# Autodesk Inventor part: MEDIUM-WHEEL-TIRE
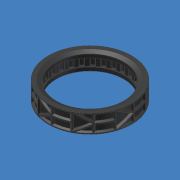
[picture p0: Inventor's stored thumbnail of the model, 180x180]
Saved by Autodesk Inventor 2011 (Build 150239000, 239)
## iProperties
Created: 2007-08
Part Number: MEDIUM-WHEEL-TIRE
Material: Rubber
Document SubType Name: Modeling
Density: 0.93 g/cm^3
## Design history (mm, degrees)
feature "Base1"
body "Solid1"
